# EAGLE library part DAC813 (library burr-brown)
Microprocessor-Compatible 12-Bit DAC
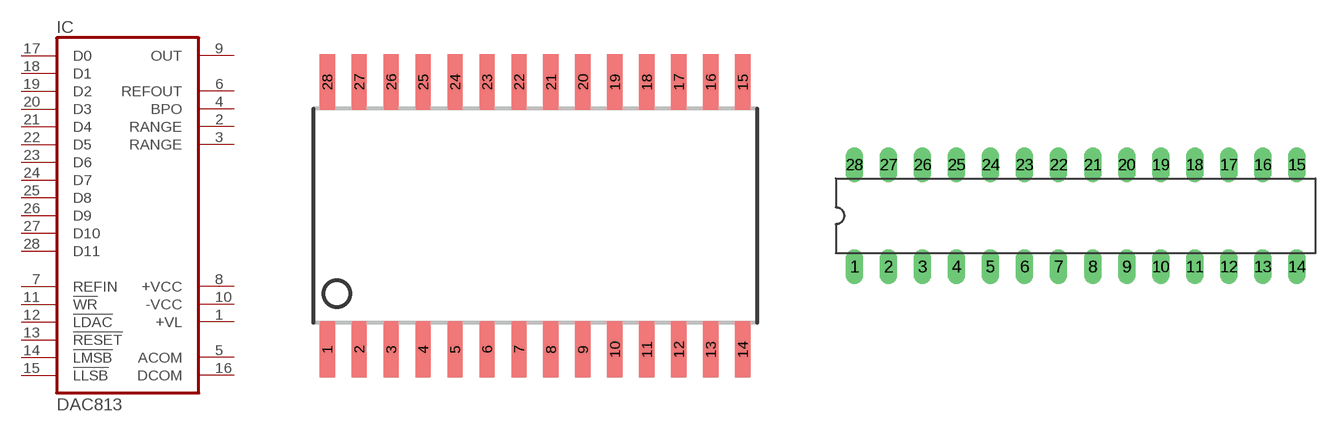
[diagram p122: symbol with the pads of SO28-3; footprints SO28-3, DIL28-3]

Designator prefix IC

## DAC813U (MF: TEXAS INSTRUMENTS; MPN: DAC813AU; OC_FARNELL: 1509910; OC_NEWARK: 74C9290)  [SO28-3]
1  +VL  pwr
2  RANGE  pas
3  RANGE  pas
4  BPO  pas
5  ACOM  pwr
6  REFOUT  out
7  REFIN  in
8  +VCC  pwr
9  OUT  out
10  -VCC  pwr
11  !WR  in
12  !LDAC  in
13  !RESET  in
14  !LMSB  in
15  !LLSB  in
16  DCOM  pwr
17  D0  in
18  D1  in
19  D2  in
20  D3  in
21  D4  in
22  D5  in
23  D6  in
24  D7  in
25  D8  in
26  D9  in
27  D10  in
28  D11  in

## DAC813P (MPN: DAC813JP; OC_FARNELL: 1295977; OC_NEWARK: 61M5756)  [DIL28-3]
Pads as for SO28-3

## Footprint SO28-3 (pad centres in mm)
Small Outline Package
smd 0.61 x 2.21: 1 -8.255,-5.315; 2 -6.985,-5.315; 3 -5.715,-5.315; 4 -4.445,-5.315; 5 -3.175,-5.315; 6 -1.905,-5.315; 7 -0.635,-5.315; 8 0.635,-5.315; 9 1.905,-5.315; 10 3.175,-5.315; 11 4.445,-5.315; 12 5.715,-5.315; 13 6.985,-5.315; 14 8.255,-5.315; 15 8.255,5.315; 16 6.985,5.315; 17 5.715,5.315; 18 4.445,5.315; 19 3.175,5.315; 20 1.905,5.315; 21 0.635,5.315; 22 -0.635,5.315; 23 -1.905,5.315; 24 -3.175,5.315; 25 -4.445,5.315; 26 -5.715,5.315; 27 -6.985,5.315; 28 -8.255,5.315

## Footprint DIL28-3 (pad centres in mm)
Dual In Line 0.3 inch
drill 0.813 long: 1 -16.51,-3.81; 2 -13.97,-3.81; 3 -11.43,-3.81; 4 -8.89,-3.81; 5 -6.35,-3.81; 6 -3.81,-3.81; 7 -1.27,-3.81; 8 1.27,-3.81; 9 3.81,-3.81; 10 6.35,-3.81; 11 8.89,-3.81; 12 11.43,-3.81; 13 13.97,-3.81; 14 16.51,-3.81; 15 16.51,3.81; 16 13.97,3.81; 17 11.43,3.81; 18 8.89,3.81; 19 6.35,3.81; 20 3.81,3.81; 21 1.27,3.81; 22 -1.27,3.81; 23 -3.81,3.81; 24 -6.35,3.81; 25 -8.89,3.81; 26 -11.43,3.81; 27 -13.97,3.81; 28 -16.51,3.81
